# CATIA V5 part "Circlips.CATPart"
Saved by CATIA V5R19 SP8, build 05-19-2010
Part number: Circlips
Publications: "Rayon_ext", "Rayon_int"
Bounding box of the stored display mesh (mm): x -13.427 to 13.427, y -16 to 13.321, z 0 to 1
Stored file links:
  F:\! CONCEPTION\PROJET\Mécanisme 544\CAO\Circlips.CATPart
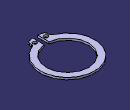
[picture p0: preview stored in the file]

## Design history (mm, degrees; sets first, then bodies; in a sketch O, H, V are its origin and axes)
Parameters
  Rayon_ext = 13.5 mm {= Rayon_int +3mm}
  Rayon_int = 10.5 mm
Body1 (main body)
  Sketch1 on xy-plane, origin (0, 0, 0), H (1, 0, 0), V (0, 1, 0)
    arc A1 centre (0, 0) radius 13.5 from (4.8879, -12.584) to (-4.8879, -12.584) ccw
    point P1 (0, 0)
    arc A2 centre (0, 0) radius 10.5 from (1.25, -10.4253) to (-1.25, -10.4253) ccw
    point P2 (0, 0)
    line L1 (-1.25, -10.4253) -> (-1.25, -16)
    point P3 (-1.25, -16)
    line L2 (-1.25, -16) -> (-3.4236, -15.6167)
    line L3 (-4.25, -14.6319) -> (-4.25, -13.5162)
    line L4 (1.25, -10.4253) -> (1.25, -16)
    line L5 (1.25, -16) -> (3.4236, -15.6167)
    line L6 (4.25, -14.6319) -> (4.25, -13.5162)
    arc A3 centre (-3.25, -14.6319) radius 1 from (-4.25, -14.6319) to (-3.4236, -15.6167) ccw
    arc A4 centre (3.25, -14.6319) radius 1 from (4.25, -14.6319) to (3.4236, -15.6167) cw
    arc A5 centre (5.25, -13.5162) radius 1 from (4.8879, -12.584) to (4.25, -13.5162) ccw
    arc A6 centre (-5.25, -13.5162) radius 1 from (-4.8879, -12.584) to (-4.25, -13.5162) cw
    circle A7 centre (2.75, -13.5) radius 1
    point P20 (-2.75, -13.5)
    circle A8 centre (-2.75, -13.5) radius 1
    radius A1 = 13.5 {= Rayon_ext}
    radius A2 = 10.5 {= Rayon_int}
    radius A3 = 1
    radius A4 = 1
    radius A5 = 1
    radius A6 = 1
    distance L1 L4 = 2.5
    distance L3 L1 = 3
    distance P20 L1 = 1.5
    radius A8 = 1
    distance P3 H = 16 {= Rayon_ext +2.5mm}
    angle L5 H = 10
    distance P20 H = 13.5 {= Rayon_ext}
    vertical: L1 V, L3 V, L4 V, L6 V
    symmetry: L6 L3 V, L1 L4 V, L5 L2 V, A8 A7 V
    tangency: A3 L3, A3 L2, A4 L6, A4 L5, A5 L6, A5 A1, A6 A1, A6 L3
    coincidence: P1 O, P2 V, P2 H
  Pad1: profile Sketch1, direction (0, 0, 1), length 1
